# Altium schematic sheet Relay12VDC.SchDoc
size A4; DocumentNumber: 3; SheetNumber: 3; SheetTotal: 4
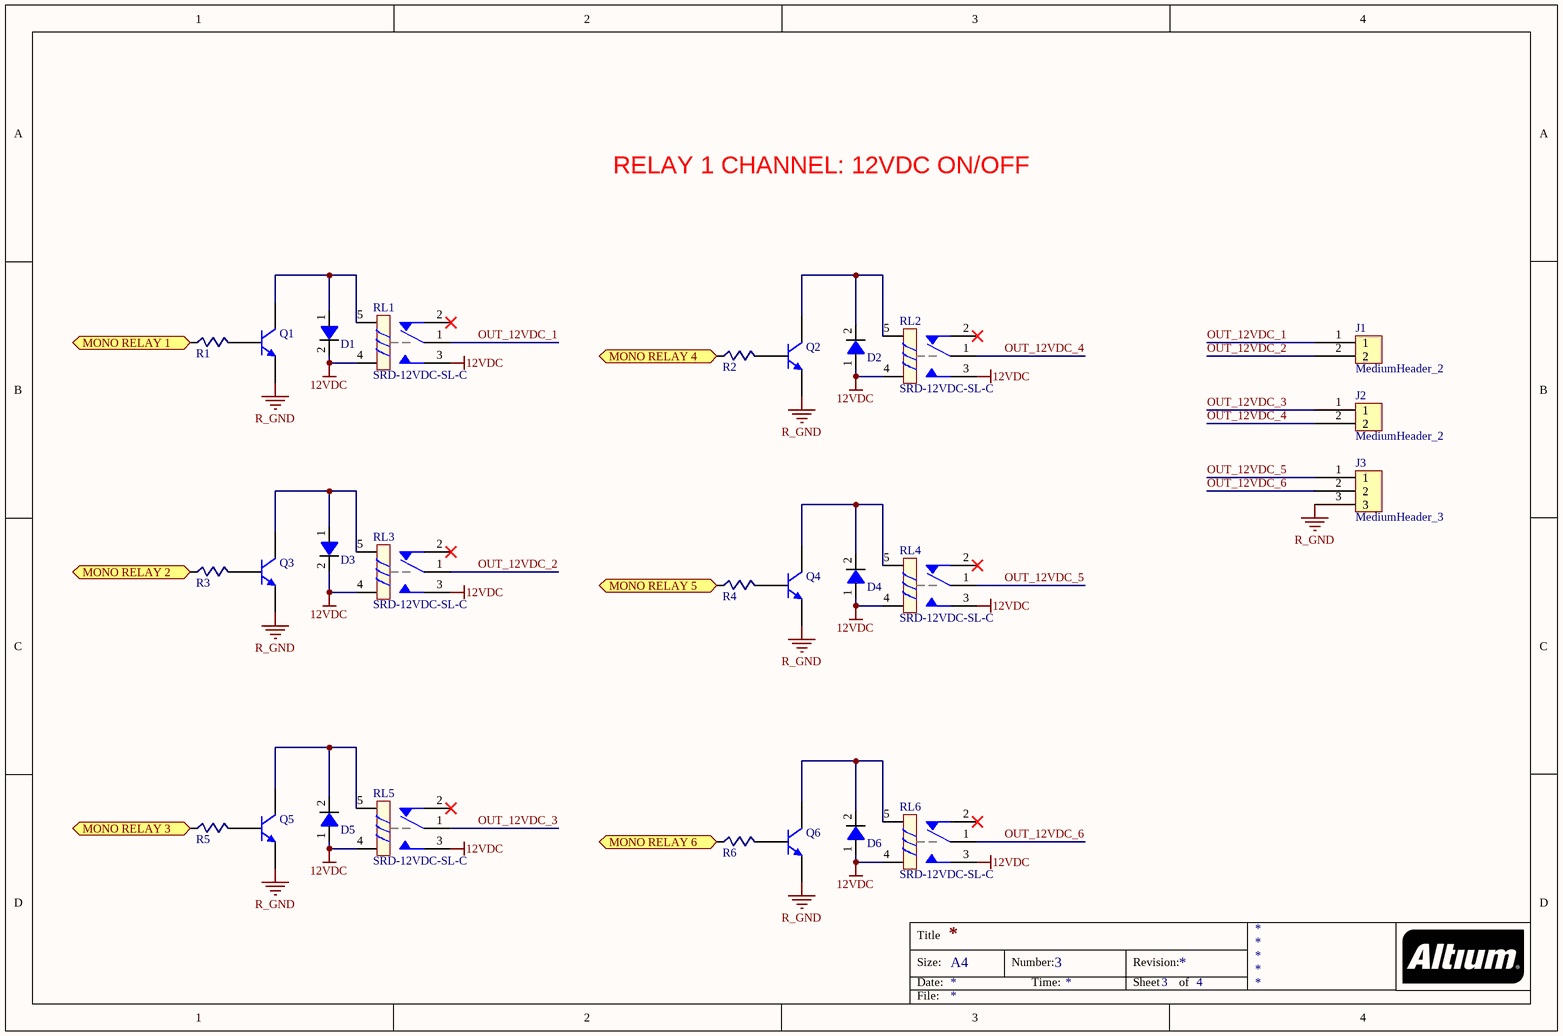
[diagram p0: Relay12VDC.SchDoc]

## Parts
D1  M7 SMD  [Diode 1N4007 SMD]  (value not drawn)
D2  M7 SMD  [Diode 1N4007 SMD]  (value not drawn)
D3  M7 SMD  [Diode 1N4007 SMD]  (value not drawn)
D4  M7 SMD  [Diode 1N4007 SMD]  (value not drawn)
D5  M7 SMD  [Diode 1N4007 SMD]  (value not drawn)
D6  M7 SMD  [Diode 1N4007 SMD]  (value not drawn)
J1  MediumHeader_2  [Medium - Header 2]
J2  MediumHeader_2  [Medium - Header 2]
J3  MediumHeader_3  [Medium - Header 3]
Q1  MMBT3904  [SOT23_L_MOD]  (value not drawn)
Q2  MMBT3904  [SOT23_L_MOD]  (value not drawn)
Q3  MMBT3904  [SOT23_L_MOD]  (value not drawn)
Q4  MMBT3904  [SOT23_L_MOD]  (value not drawn)
Q5  MMBT3904  [SOT23_L_MOD]  (value not drawn)
Q6  MMBT3904  [SOT23_L_MOD]  (value not drawn)
R1  R_1K_0603  [RES-SMD-0603]  (value not drawn)
R2  R_1K_0603  [RES-SMD-0603]  (value not drawn)
R3  R_1K_0603  [RES-SMD-0603]  (value not drawn)
R4  R_1K_0603  [RES-SMD-0603]  (value not drawn)
R5  R_1K_0603  [RES-SMD-0603]  (value not drawn)
R6  R_1K_0603  [RES-SMD-0603]  (value not drawn)
RL1  SRD-12VDC-SL-C  [RELAY SRD-12VDC]
RL2  SRD-12VDC-SL-C  [RELAY SRD-12VDC]
RL3  SRD-12VDC-SL-C  [RELAY SRD-12VDC]
RL4  SRD-12VDC-SL-C  [RELAY SRD-12VDC]
RL5  SRD-12VDC-SL-C  [RELAY SRD-12VDC]
RL6  SRD-12VDC-SL-C  [RELAY SRD-12VDC]

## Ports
MONO RELAY 1, MONO RELAY 2, MONO RELAY 3, MONO RELAY 4, MONO RELAY 5, MONO RELAY 6

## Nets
12VDC: D1.2 D2.1 D3.2 D4.1 D5.1 D6.1 RL1.3 RL1.4 RL2.3 RL2.4 RL3.3 RL3.4 RL4.3 RL4.4 RL5.3 RL5.4 RL6.3 RL6.4
R_GND: J3.3 Q1.2(E) Q2.2(E) Q3.2(E) Q4.2(E) Q5.2(E) Q6.2(E)
MONO RELAY 1: R1.1 ; port MONO RELAY 1
MONO RELAY 2: R3.1 ; port MONO RELAY 2
MONO RELAY 3: R5.1 ; port MONO RELAY 3
MONO RELAY 4: R2.1 ; port MONO RELAY 4
MONO RELAY 5: R4.1 ; port MONO RELAY 5
MONO RELAY 6: R6.1 ; port MONO RELAY 6
OUT_12VDC_1: J1.1 RL1.1
OUT_12VDC_2: J1.2 RL3.1
OUT_12VDC_3: J2.1 RL5.1
OUT_12VDC_4: J2.2 RL2.1
OUT_12VDC_5: J3.1 RL4.1
OUT_12VDC_6: J3.2 RL6.1
NetD1_1: D1.1 Q1.3(C) RL1.5
NetD2_2: D2.2 Q2.3(C) RL2.5
NetD3_1: D3.1 Q3.3(C) RL3.5
NetD4_2: D4.2 Q4.3(C) RL4.5
NetD5_2: D5.2 Q5.3(C) RL5.5
NetD6_2: D6.2 Q6.3(C) RL6.5
NetQ1_1: Q1.1(B) R1.2
NetQ2_1: Q2.1(B) R2.2
NetQ3_1: Q3.1(B) R3.2
NetQ4_1: Q4.1(B) R4.2
NetQ5_1: Q5.1(B) R5.2
NetQ6_1: Q6.1(B) R6.2

Not connected (* = marked no-connect by the designer): RL1 2*; RL2 2*; RL3 2*; RL4 2*; RL5 2*; RL6 2*

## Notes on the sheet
- RELAY 1 CHANNEL: 12VDC ON/OFF

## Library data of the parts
D1-D6 = Diode_1N4007: DIODE GEN PURP 1KV 1A DO214AC
Q1-Q6 = MMBT3904: TRANSISTOR GP NPN AMP SOT-23
R1-R6 = RES0603_1K: RES 1K OHM 1/10W 1% 0603 SMD
RL1-RL6 = RELAY SRD-12VDC: Relay SPDT,10A - 12VDC 5 Pin; Value: Relay SPDT, 10A, 12V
